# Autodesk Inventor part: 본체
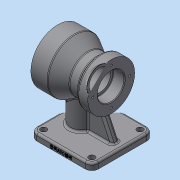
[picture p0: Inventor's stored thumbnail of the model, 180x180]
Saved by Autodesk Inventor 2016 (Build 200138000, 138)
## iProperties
Created: 2019-01
Part Number: 본체
Material: 일반
Document SubType Name: Modeling
Designer: Administrator
Density: 1 g/cm^3
Appearance: 기본값
Author: Administrator
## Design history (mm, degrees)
sketch "스케치1"
  geometry: L1 (-46, -46)-(46, -46); L2 (46, -46)-(46, 46); L3 (46, 46)-(-46, 46); L4 (-46, 46)-(-46, -46); L5 (-46, -46)-(46, 46); L6 (46, -46)-(-46, 46); 1 further point
  constraints: 12 end point, 2 midpoint, 2 parallel, 1 horizontal, 1 perpendicular
  dimensions: "d0" = 92 distance of L3.end L2.end; "d1" = 92 distance of L2.end L1.end
extrude "돌출1" new body sketch "스케치1" distance "d2" = 10; taper "d3" = 0 deg
sketch "스케치2"
  geometry: L1 (-46, 46)-(-46, -46) reference; C1 r 16 at (-16, 0); 1 further point
  constraints: 1 centre point, 1 horizontal alignment
  dimensions: "d4" = 32 diameter of C1; "d5" = 30 distance from line of L1 C1.centre
sketch "스케치3"
  geometry: L1 (56.031, 80)-(-45.484, 80); L2 (51, 80)-(51, 120); L3 (51, 120)-(26, 120); L4 (26, 120)-(5.215, 108); L5 (5.215, 108)-(-8.126, 108); L6 (-14, 115)-(-29, 115); L7 (-29, 115)-(-29, 80); L8 (-8.126, 108)-(-14, 115); L9 (46, 0)-(-46, 0) reference; L10 (46, 0)-(46, 10) reference; 1 further point
  constraints: 16 end point, 3 perpendicular, 2 parallel, 2 point on line, 1 horizontal
  dimensions: "d6" = 40 distance of L2.start L2.end; "d7" = 25 distance of L2.end L3.end; "d8" = 80 distance between parallel lines of L7 L2; "d9" = 35 distance of L6.end L7.end; "d10" = 15 distance of L6.start L6.end; "d11" = 30 deg angle of L4 L5; "d12" = 50 deg angle of L5 L8; "d13" = 56 diameter of L5 L1; "d14" = 80 distance between parallel lines of L9 L1; "d15" = 5 distance between parallel lines of L10 L2
revolve "회전1" sketch "스케치3" stored, may be unused: angle "d16" = 90 deg
extrude "돌출2" join sketch "스케치2" stored distance "d17" = 10; taper "d18" = 0 deg
sketch "스케치5"
  geometry: L1 (-46, 10)-(46, 10) reference; L2 (-36, 10)-(-21.907, 40.222); L3 (-46, 0)-(-46, 10) reference; 1 further point
  constraints: 2 end point, 1 point on line
  dimensions: "d21" = 115 deg angle of L1 L2; "d22" = 10 distance from line of L3 L2.start
feature "리브1" sketch "스케치5" dims "d23" = 1, "d24" = 10, "d25" = 0, "d26" = 0, "d27" = 1, "d28" = 1
hole "구멍1" diameter "d31" = 52; stored, may be unused: countersink angle "d35" = 90 deg, drill point angle "d37" = 0 deg; dims "d29" = 10, "d30" = 10, "d32" = 6, "d33" = 4, "d34" = 2, "d36" = 20
hole "구멍2" diameter "d40" = 40; stored, may be unused: countersink angle "d44" = 90 deg, drill point angle "d46" = 0 deg; dims "d38" = 10, "d39" = 10, "d41" = 6, "d42" = 4, "d43" = 2, "d45" = 17
hole "구멍3" diameter "d49" = 32; stored, may be unused: countersink angle "d53" = 90 deg, drill point angle "d55" = 0 deg; dims "d47" = 10, "d48" = 10, "d50" = 6, "d51" = 4, "d52" = 2, "d54" = 17
sketch "스케치6"
  geometry: L1 (0, 0)-(33, 0); C1 r 20 at (0, 0) reference; 2 further points
  constraints: 2 end point, 1 coincident, 1 horizontal
  dimensions: "d56" = 33 distance of L1.start L1.end
hole "구멍4" sketch "스케치6" at (33, 0) diameter "d57" = 3.242; stored, may be unused: countersink angle "d61" = 90 deg, drill point angle "d63" = 118 deg; dims "d58" = 9, "d59" = 4, "d60" = 2, "d62" = 11
sketch "스케치7"
  geometry: L1 (0, 0)-(-27.5, 0); 2 further points
  constraints: 2 end point, 1 coincident, 1 horizontal
  dimensions: "d67" = 27.5 distance of L1.start L1.end
hole "구멍5" sketch "스케치7" at (-27.5, 0) diameter "d68" = 3.242; stored, may be unused: countersink angle "d72" = 90 deg, drill point angle "d74" = 118 deg; dims "d69" = 9, "d70" = 4, "d71" = 2, "d73" = 11
chamfer "모따기1" distance "d78" = 1; stored, may be unused: second distance "d79" = 2, angle "d80" = 45 deg
fillet "모깎기1" dims "d81" = 1, "d82" = 0.6
fillet "모깎기2" dims "d83" = 10, "d84" = 3
fillet "모깎기3" dims "d85" = 3
sketch "스케치8"
  geometry: A1 r 10 centre (36, 36) between (46, 36) and (36, 46) reference; A2 r 10 centre (-36, 36) between (-36, 46) and (-46, 36) reference; A3 r 10 centre (-36, -36) between (-46, -36) and (-36, -46) reference; A4 r 10 centre (36, -36) between (36, -46) and (46, -36) reference; 5 further points
  constraints: 4 coincident
hole "구멍6" sketch "스케치8" at (36, 36), (-36, 36), (-36, -36), (36, -36) diameter "d86" = 9; stored, may be unused: countersink angle "d90" = 90 deg, drill point angle "d92" = 0 deg; dims "d87" = 6, "d88" = 4, "d89" = 2, "d91" = 8
sketch "스케치9"
  geometry: L1 (0, 0)-(72, 0) reference; L2 (-10, 10)-(-10, 0) reference; 2 further points
  constraints: 1 other
  dimensions: "d93" = 4 distance from line of L1 point (36, 4); "d94" = 46 distance from line of L2 point (36, 4)
feature "엠보싱1" sketch "스케치9" dims "d0" = 92, "d1" = 92, "d95" = 0.5, "d96" = 0
fillet "모깎기4" dims "d97" = 3
node "솔리드1"
pattern_circular "원형 패턴1" dims angle "d65" = 360 deg
pattern_circular "원형 패턴2" dims angle "d76" = 360 deg
